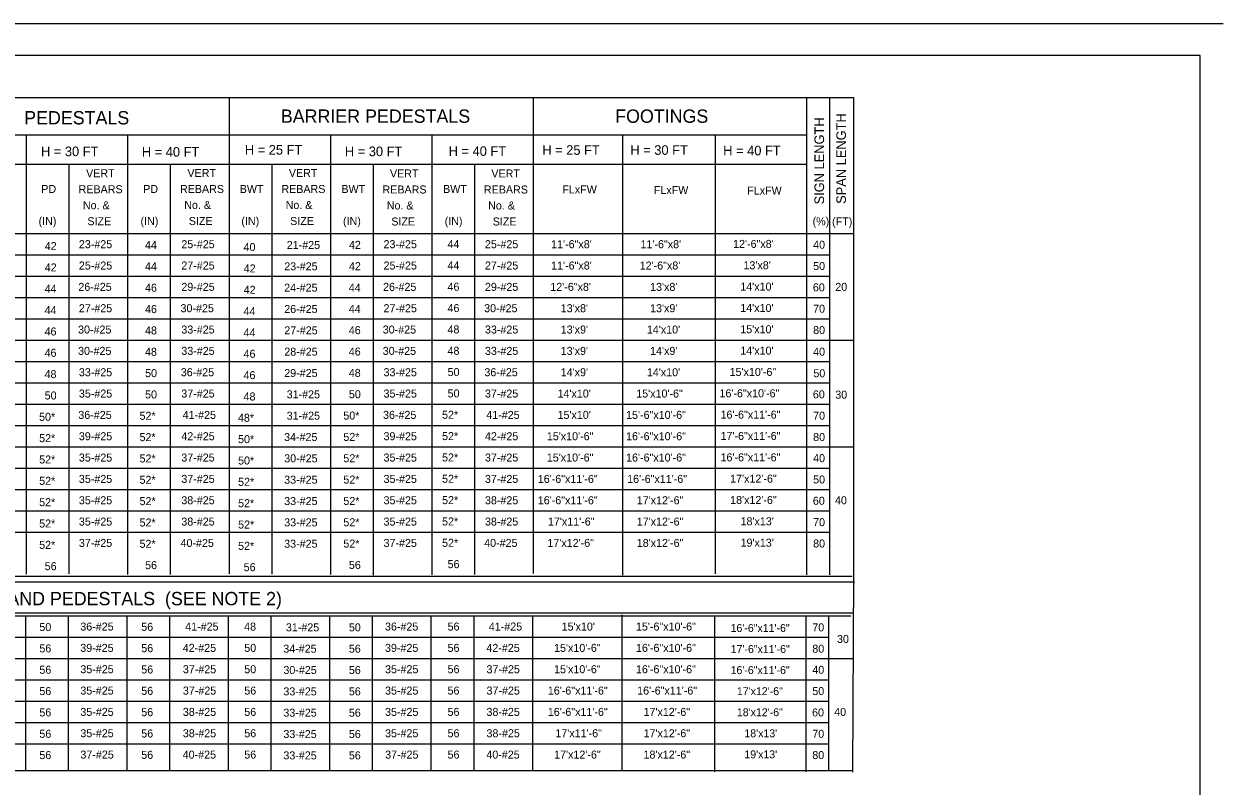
# Model space of a CAD drawing. Extents: x -17866409 to 26050223, y -3454119 to 12035012.
# Drawn here: x 31.44 to 68.89, y 19.52 to 43.33 of the extents above; entities that cross this region are included whole.
import ezdxf

# ---------------------------------------------------------------- set-up
doc = ezdxf.new("R2010")
doc.units = 0
doc.layers.add('1', color=7, linetype='Continuous')
doc.layers.add('2', color=7, linetype='Continuous')

msp = doc.modelspace()

# ---------------------------------------------------------------- linework, layer by layer
at = {"layer": '1'}
for p, q in [((68.892, 43.325), (0, 43.325)), ((68.183, 42.342), (3.6, 42.342)), ((68.183, 1.017), (68.183, 42.342))]:
    msp.add_line(p, q, dxfattribs=at)
at = {"layer": '2'}
for p, q in [((9.106, 41.029), (57.356, 41.029)), ((37.856, 26.149), (37.856, 41.029)), ((47.356, 26.154), (47.356, 41.029)), ((55.897, 26.12), (55.897, 41.029)), ((56.606, 26.117), (56.606, 41.029)), ((57.356, 26.118), (57.356, 41.029)), ((11.106, 39.862), (55.897, 39.862)), ((31.522, 26.132), (31.522, 39.862)), ((34.689, 26.13), (34.689, 39.862)), ((41.022, 26.129), (41.022, 39.862)), ((44.189, 26.117), (44.189, 39.862)), ((50.147, 26.107), (50.147, 39.862)), ((53.039, 26.145), (53.039, 39.862)), ((20.356, 38.945), (43.314, 38.945)), ((32.856, 26.149), (32.856, 38.945)), ((36.022, 26.13), (36.022, 38.945)), ((39.189, 26.139), (39.189, 38.945)), ((42.356, 26.107), (42.356, 38.945)), ((43.331, 38.945), (55.897, 38.945)), ((45.522, 26.126), (45.522, 38.945)), ((9.106, 36.779), (57.356, 36.779)), ((10.106, 36.112), (56.606, 36.112)), ((10.106, 35.445), (56.606, 35.445)), ((10.106, 34.779), (56.606, 34.779)), ((10.106, 34.112), (56.606, 34.112)), ((9.106, 33.445), (57.356, 33.445)), ((10.106, 32.779), (56.606, 32.779)), ((10.106, 32.112), (56.606, 32.112)), ((10.106, 31.445), (56.606, 31.445)), ((10.106, 30.779), (56.606, 30.779)), ((9.106, 30.112), (57.356, 30.112)), ((10.106, 29.445), (56.606, 29.445)), ((10.106, 28.779), (56.606, 28.779)), ((10.106, 28.112), (56.606, 28.112)), ((10.082, 27.445), (56.582, 27.445)), ((9.047, 26.072), (57.311, 26.072)), ((9.13, 25.892), (57.38, 25.892)), ((57.333, 19.95), (57.356, 26.118)), ((9.067, 24.83), (57.267, 24.83)), ((9.101, 24.93), (57.351, 24.93)), ((31.498, 20.005), (31.498, 24.807)), ((32.831, 19.977), (32.831, 24.807)), ((34.664, 19.977), (34.664, 24.807)), ((35.998, 19.991), (35.998, 24.846)), ((37.831, 20.005), (37.831, 24.807)), ((39.164, 19.977), (39.164, 24.846)), ((40.998, 19.977), (40.998, 24.826)), ((42.331, 20.005), (42.331, 24.826)), ((44.164, 19.991), (44.164, 24.826)), ((45.498, 19.991), (45.498, 24.846)), ((47.331, 19.977), (47.331, 24.826)), ((50.123, 19.991), (50.123, 24.861)), ((53.014, 19.964), (53.014, 24.826)), ((55.873, 19.964), (55.873, 24.826)), ((56.581, 19.991), (56.581, 24.833)), ((10.081, 24.166), (56.581, 24.166)), ((9.081, 23.499), (57.331, 23.499)), ((10.081, 22.833), (56.581, 22.833)), ((10.081, 22.166), (56.581, 22.166)), ((10.081, 21.499), (56.581, 21.499)), ((10.081, 20.833), (56.581, 20.833)), ((9.065, 19.997), (57.329, 19.997))]:
    msp.add_line(p, q, dxfattribs=at)

# ---------------------------------------------------------------- texts
for s, height, p in [('PEDESTALS', 0.4166, (31.447, 40.187)), ('BARRIER PEDESTALS', 0.41665, (39.464, 40.237)), ('FOOTINGS', 0.4166, (49.906, 40.237)), ('H = 30 FT', 0.3, (31.972, 39.195)), ('H = 40 FT', 0.3, (35.122, 39.179)), ('H = 25 FT', 0.3, (38.339, 39.245)), ('H = 30 FT', 0.3, (41.464, 39.195)), ('H = 40 FT', 0.3, (44.706, 39.204)), ('H = 25 FT', 0.3, (47.631, 39.237)), ('H = 30 FT', 0.3, (50.381, 39.237)), ('H = 40 FT', 0.3, (53.281, 39.22)), ('VERT', 0.25, (33.381, 38.537)), ('VERT', 0.25, (36.547, 38.545)), ('VERT', 0.25, (39.714, 38.545)), ('VERT', 0.25, (42.872, 38.529)), ('VERT', 0.25, (46.039, 38.529)), ('PD', 0.25, (31.981, 38.045)), ('REBARS', 0.25, (33.147, 38.037)), ('PD', 0.25, (35.164, 38.045)), ('REBARS', 0.25, (36.314, 38.045)), ('BWT', 0.25, (38.181, 38.045)), ('REBARS', 0.25, (39.481, 38.045)), ('BWT', 0.25, (41.356, 38.045)), ('REBARS', 0.25, (42.639, 38.029)), ('BWT', 0.25, (44.531, 38.045)), ('REBARS', 0.25, (45.806, 38.029)), ('FLxFW', 0.25, (48.256, 38.029)), ('FLxFW', 0.25, (51.114, 38.012)), ('FLxFW', 0.25, (54.031, 37.995)), ('No. &', 0.25, (33.281, 37.537)), ('No. &', 0.25, (36.447, 37.545)), ('No. &', 0.25, (39.614, 37.545)), ('No. &', 0.25, (42.772, 37.529)), ('No. &', 0.25, (45.939, 37.529)), ('(IN)', 0.25, (31.897, 37.045)), ('SIZE', 0.25, (33.422, 37.037)), ('(IN)', 0.25, (35.081, 37.045)), ('SIZE', 0.25, (36.589, 37.045)), ('(IN)', 0.25, (38.231, 37.045)), ('SIZE', 0.25, (39.756, 37.045)), ('(IN)', 0.25, (41.406, 37.045)), ('SIZE', 0.25, (42.914, 37.029)), ('(IN)', 0.25, (44.581, 37.045)), ('SIZE', 0.25, (46.081, 37.029)), ('(%)', 0.25, (56.072, 37.037)), ('(FT)', 0.25, (56.681, 37.029)), ('42', 0.25, (32.089, 36.26)), ('23-#25', 0.25, (33.156, 36.32)), ('44', 0.25, (35.22, 36.292)), ('25-#25', 0.25, (36.356, 36.32)), ('40', 0.25, (38.299, 36.229)), ('21-#25', 0.25, (39.649, 36.295)), ('42', 0.25, (41.591, 36.299)), ('23-#25', 0.25, (42.672, 36.32)), ('44', 0.25, (44.669, 36.324)), ('25-#25', 0.25, (45.839, 36.32)), ('11\'-6"x8\'', 0.25, (47.906, 36.32)), ('11\'-6"x8\'', 0.25, (50.697, 36.32)), ('12\'-6"x8\'', 0.25, (53.589, 36.329)), ('40', 0.25, (56.089, 36.304)), ('42', 0.25, (32.089, 35.594)), ('25-#25', 0.25, (33.156, 35.654)), ('44', 0.25, (35.22, 35.626)), ('27-#25', 0.25, (36.356, 35.654)), ('42', 0.25, (38.304, 35.562)), ('23-#25', 0.25, (39.571, 35.629)), ('42', 0.25, (41.591, 35.633)), ('25-#25', 0.25, (42.672, 35.654)), ('44', 0.25, (44.669, 35.658)), ('27-#25', 0.25, (45.839, 35.654)), ('11\'-6"x8\'', 0.25, (47.906, 35.654)), ('12\'-6"x8\'', 0.25, (50.672, 35.654)), ("13'x8'", 0.25, (53.914, 35.662)), ('50', 0.25, (56.089, 35.637)), ('26-#25', 0.25, (33.139, 34.987)), ('46', 0.25, (35.221, 34.959)), ('29-#25', 0.25, (36.356, 34.987)), ('24-#25', 0.25, (39.568, 34.962)), ('44', 0.25, (41.586, 34.966)), ('26-#25', 0.25, (42.656, 34.987)), ('46', 0.25, (44.67, 34.991)), ('29-#25', 0.25, (45.839, 34.987)), ('12\'-6"x8\'', 0.25, (47.881, 34.987)), ("13'x8'", 0.25, (50.997, 34.987)), ("14'x10'", 0.25, (53.814, 34.995)), ('60', 0.25, (56.081, 34.97)), ('20', 0.25, (56.781, 34.987)), ('44', 0.25, (32.084, 34.927)), ('42', 0.25, (38.304, 34.896)), ('44', 0.25, (32.084, 34.26)), ('27-#25', 0.25, (33.156, 34.32)), ('46', 0.25, (35.221, 34.292)), ('30-#25', 0.25, (36.331, 34.32)), ('44', 0.25, (38.299, 34.229)), ('26-#25', 0.25, (39.57, 34.295)), ('44', 0.25, (41.586, 34.299)), ('27-#25', 0.25, (42.672, 34.32)), ('46', 0.25, (44.67, 34.324)), ('30-#25', 0.25, (45.814, 34.32)), ("13'x8'", 0.25, (48.206, 34.32)), ("13'x9'", 0.25, (50.997, 34.32)), ("14'x10'", 0.25, (53.814, 34.329)), ('70', 0.25, (56.089, 34.304)), ('46', 0.25, (32.084, 33.594)), ('30-#25', 0.25, (33.131, 33.654)), ('48', 0.25, (35.221, 33.626)), ('33-#25', 0.25, (36.356, 33.654)), ('44', 0.25, (38.299, 33.562)), ('27-#25', 0.25, (39.573, 33.629)), ('46', 0.25, (41.586, 33.633)), ('30-#25', 0.25, (42.647, 33.654)), ('48', 0.25, (44.67, 33.658)), ('33-#25', 0.25, (45.839, 33.654)), ("13'x9'", 0.25, (48.206, 33.654)), ("14'x10'", 0.25, (50.897, 33.654)), ("15'x10'", 0.25, (53.814, 33.662)), ('80', 0.25, (56.089, 33.637)), ('46', 0.25, (32.084, 32.927)), ('30-#25', 0.25, (33.131, 32.987)), ('48', 0.25, (35.221, 32.959)), ('33-#25', 0.25, (36.356, 32.987)), ('46', 0.25, (38.299, 32.896)), ('28-#25', 0.25, (39.572, 32.962)), ('46', 0.25, (41.586, 32.966)), ('30-#25', 0.25, (42.647, 32.987)), ('48', 0.25, (44.67, 32.991)), ('33-#25', 0.25, (45.839, 32.987)), ("13'x9'", 0.25, (48.206, 32.987)), ("14'x9'", 0.25, (50.997, 32.987)), ("14'x10'", 0.25, (53.814, 32.995)), ('40', 0.25, (56.089, 32.962)), ('15\'x10\'-6"', 0.25, (53.481, 32.329)), ('48', 0.25, (32.084, 32.26)), ('33-#25', 0.25, (33.156, 32.32)), ('50', 0.25, (35.224, 32.292)), ('36-#25', 0.25, (36.339, 32.32)), ('46', 0.25, (38.299, 32.229)), ('29-#25', 0.25, (39.57, 32.295)), ('48', 0.25, (41.586, 32.299)), ('33-#25', 0.25, (42.672, 32.32)), ('50', 0.25, (44.673, 32.324)), ('36-#25', 0.25, (45.822, 32.32)), ("14'x9'", 0.25, (48.206, 32.32)), ("14'x10'", 0.25, (50.897, 32.32)), ('50', 0.25, (56.097, 32.287)), ('50', 0.25, (32.088, 31.594)), ('35-#25', 0.25, (33.156, 31.654)), ('50', 0.25, (35.224, 31.626)), ('37-#25', 0.25, (36.356, 31.654)), ('31-#25', 0.25, (39.646, 31.629)), ('50', 0.25, (41.59, 31.633)), ('35-#25', 0.25, (42.672, 31.654)), ('50', 0.25, (44.673, 31.658)), ('37-#25', 0.25, (45.839, 31.654)), ("14'x10'", 0.25, (48.106, 31.654)), ('15\'x10\'-6"', 0.25, (50.564, 31.654)), ('16\'-6"x10\'-6"', 0.25, (53.164, 31.662)), ('60', 0.25, (56.081, 31.629)), ('30', 0.25, (56.781, 31.62)), ('48', 0.25, (38.299, 31.562)), ('50*', 0.25, (31.913, 30.927)), ('36-#25', 0.25, (33.139, 30.987)), ('52*', 0.25, (35.051, 30.959)), ('41-#25', 0.25, (36.397, 30.987)), ('48*', 0.25, (38.125, 30.896)), ('31-#25', 0.25, (39.646, 30.962)), ('50*', 0.25, (41.415, 30.966)), ('36-#25', 0.25, (42.656, 30.987)), ('52*', 0.25, (44.5, 30.991)), ('41-#25', 0.25, (45.881, 30.987)), ("15'x10'", 0.25, (48.106, 30.987)), ('15\'-6"x10\'-6"', 0.25, (50.247, 30.987)), ('16\'-6"x11\'-6"', 0.25, (53.197, 30.995)), ('70', 0.25, (56.089, 30.962)), ('52*', 0.25, (31.915, 30.26)), ('39-#25', 0.25, (33.156, 30.32)), ('52*', 0.25, (35.051, 30.292)), ('42-#25', 0.25, (36.356, 30.32)), ('50*', 0.25, (38.128, 30.229)), ('34-#25', 0.25, (39.565, 30.295)), ('52*', 0.25, (41.416, 30.299)), ('39-#25', 0.25, (42.672, 30.32)), ('52*', 0.25, (44.5, 30.324)), ('42-#25', 0.25, (45.839, 30.32)), ('15\'x10\'-6"', 0.25, (47.772, 30.32)), ('16\'-6"x10\'-6"', 0.25, (50.247, 30.32)), ('17\'-6"x11\'-6"', 0.25, (53.197, 30.329)), ('80', 0.25, (56.089, 30.295)), ('52*', 0.25, (31.915, 29.594)), ('35-#25', 0.25, (33.156, 29.654)), ('52*', 0.25, (35.051, 29.626)), ('37-#25', 0.25, (36.356, 29.654)), ('50*', 0.25, (38.128, 29.562)), ('30-#25', 0.25, (39.569, 29.629)), ('52*', 0.25, (41.416, 29.633)), ('35-#25', 0.25, (42.672, 29.654)), ('52*', 0.25, (44.5, 29.658)), ('37-#25', 0.25, (45.839, 29.654)), ('15\'x10\'-6"', 0.25, (47.772, 29.654)), ('16\'-6"x10\'-6"', 0.25, (50.247, 29.654)), ('16\'-6"x11\'-6"', 0.25, (53.197, 29.662)), ('40', 0.25, (56.089, 29.637)), ('35-#25', 0.25, (33.156, 28.987)), ('52*', 0.25, (35.051, 28.959)), ('37-#25', 0.25, (36.356, 28.987)), ('33-#25', 0.25, (39.568, 28.962)), ('52*', 0.25, (41.416, 28.966)), ('35-#25', 0.25, (42.672, 28.987)), ('52*', 0.25, (44.5, 28.991)), ('37-#25', 0.25, (45.839, 28.987)), ('16\'-6"x11\'-6"', 0.25, (47.489, 28.987)), ('16\'-6"x11\'-6"', 0.25, (50.281, 28.987)), ('17\'x12\'-6"', 0.25, (53.497, 28.995)), ('50', 0.25, (56.089, 28.97)), ('52*', 0.25, (31.915, 28.927)), ('52*', 0.25, (38.129, 28.896)), ('52*', 0.25, (31.915, 28.26)), ('35-#25', 0.25, (33.156, 28.32)), ('52*', 0.25, (35.051, 28.292)), ('38-#25', 0.25, (36.356, 28.32)), ('52*', 0.25, (38.129, 28.229)), ('33-#25', 0.25, (39.568, 28.295)), ('52*', 0.25, (41.416, 28.299)), ('35-#25', 0.25, (42.672, 28.32)), ('52*', 0.25, (44.5, 28.324)), ('38-#25', 0.25, (45.839, 28.32)), ('16\'-6"x11\'-6"', 0.25, (47.489, 28.32)), ('17\'x12\'-6"', 0.25, (50.581, 28.32)), ('18\'x12\'-6"', 0.25, (53.497, 28.329)), ('60', 0.25, (56.081, 28.304)), ('40', 0.25, (56.772, 28.32)), ('52*', 0.25, (31.915, 27.594)), ('35-#25', 0.25, (33.156, 27.654)), ('52*', 0.25, (35.051, 27.626)), ('38-#25', 0.25, (36.356, 27.654)), ('52*', 0.25, (38.129, 27.562)), ('33-#25', 0.25, (39.568, 27.629)), ('52*', 0.25, (41.416, 27.633)), ('35-#25', 0.25, (42.672, 27.654)), ('52*', 0.25, (44.5, 27.658)), ('38-#25', 0.25, (45.839, 27.654)), ('17\'x11\'-6"', 0.25, (47.806, 27.654)), ('17\'x12\'-6"', 0.25, (50.581, 27.654)), ("18'x13'", 0.25, (53.822, 27.662)), ('70', 0.25, (56.089, 27.637)), ('52*', 0.25, (31.915, 26.927)), ('37-#25', 0.25, (33.156, 26.987)), ('52*', 0.25, (35.051, 26.959)), ('40-#25', 0.25, (36.331, 26.987)), ('52*', 0.25, (38.129, 26.896)), ('33-#25', 0.25, (39.568, 26.962)), ('52*', 0.25, (41.416, 26.966)), ('37-#25', 0.25, (42.672, 26.987)), ('52*', 0.25, (44.5, 26.991)), ('40-#25', 0.25, (45.814, 26.987)), ('17\'x12\'-6"', 0.25, (47.789, 26.987)), ('18\'x12\'-6"', 0.25, (50.581, 26.987)), ("19'x13'", 0.25, (53.822, 26.995)), ('80', 0.25, (56.089, 26.97)), ('56', 0.25, (32.088, 26.26)), ('56', 0.25, (35.224, 26.292)), ('56', 0.25, (38.303, 26.229)), ('56', 0.25, (41.59, 26.299)), ('56', 0.25, (44.673, 26.324)), ('* ALTERNATIVE POSTS AND PEDESTALS  (SEE NOTE 2)', 0.41665, (24.544, 25.164)), ('50', 0.25, (31.922, 24.358)), ('36-#25', 0.25, (33.2, 24.374)), ('56', 0.25, (35.105, 24.366)), ('41-#25', 0.25, (36.477, 24.374)), ('48', 0.25, (38.318, 24.374)), ('31-#25', 0.25, (39.622, 24.349)), ('50', 0.25, (41.588, 24.349)), ('36-#25', 0.25, (42.717, 24.374)), ('56', 0.25, (44.672, 24.374)), ('41-#25', 0.25, (45.96, 24.374)), ("15'x10'", 0.25, (48.234, 24.374)), ('15\'-6"x10\'-6"', 0.25, (50.556, 24.374)), ('16\'-6"x11\'-6"', 0.24674, (53.511, 24.33)), ('70', 0.25, (56.064, 24.349)), ('30', 0.25, (56.835, 23.987)), ('56', 0.25, (31.922, 23.691)), ('39-#25', 0.25, (33.2, 23.708)), ('56', 0.25, (35.105, 23.699)), ('42-#25', 0.25, (36.401, 23.708)), ('50', 0.25, (38.322, 23.708)), ('34-#25', 0.25, (39.54, 23.683)), ('56', 0.25, (41.588, 23.683)), ('39-#25', 0.25, (42.717, 23.708)), ('56', 0.25, (44.672, 23.708)), ('42-#25', 0.25, (45.884, 23.708)), ('15\'x10\'-6"', 0.25, (47.998, 23.708)), ('16\'-6"x10\'-6"', 0.25, (50.556, 23.708)), ('17\'-6"x11\'-6"', 0.24674, (53.513, 23.672)), ('80', 0.25, (56.064, 23.683)), ('56', 0.25, (31.922, 23.024)), ('35-#25', 0.25, (33.202, 23.041)), ('56', 0.25, (35.105, 23.033)), ('37-#25', 0.25, (36.404, 23.041)), ('50', 0.25, (38.322, 23.041)), ('30-#25', 0.25, (39.544, 23.016)), ('56', 0.25, (41.588, 23.016)), ('35-#25', 0.25, (42.719, 23.041)), ('56', 0.25, (44.672, 23.041)), ('37-#25', 0.25, (45.888, 23.041)), ('15\'x10\'-6"', 0.25, (47.998, 23.041)), ('16\'-6"x10\'-6"', 0.25, (50.556, 23.041)), ('16\'-6"x11\'-6"', 0.24674, (53.511, 23.015)), ('40', 0.25, (56.064, 23.024)), ('56', 0.25, (31.922, 22.358)), ('35-#25', 0.25, (33.202, 22.374)), ('56', 0.25, (35.105, 22.366)), ('37-#25', 0.25, (36.404, 22.374)), ('56', 0.25, (38.322, 22.374)), ('33-#25', 0.25, (39.543, 22.349)), ('56', 0.25, (41.588, 22.349)), ('35-#25', 0.25, (42.719, 22.374)), ('56', 0.25, (44.672, 22.374)), ('37-#25', 0.25, (45.888, 22.374)), ('16\'-6"x11\'-6"', 0.25, (47.803, 22.374)), ('16\'-6"x11\'-6"', 0.25, (50.594, 22.374)), ('17\'x12\'-6"', 0.2467, (53.708, 22.357)), ('50', 0.25, (56.064, 22.358)), ('56', 0.25, (31.922, 21.691)), ('35-#25', 0.25, (33.202, 21.708)), ('56', 0.25, (35.105, 21.699)), ('38-#25', 0.25, (36.403, 21.708)), ('56', 0.25, (38.322, 21.708)), ('33-#25', 0.25, (39.543, 21.683)), ('56', 0.25, (41.588, 21.683)), ('35-#25', 0.25, (42.719, 21.708)), ('56', 0.25, (44.672, 21.708)), ('38-#25', 0.25, (45.887, 21.708)), ('16\'-6"x11\'-6"', 0.25, (47.803, 21.708)), ('17\'x12\'-6"', 0.25, (50.792, 21.708)), ('18\'x12\'-6"', 0.2467, (53.708, 21.699)), ('60', 0.25, (56.056, 21.691)), ('40', 0.25, (56.748, 21.708)), ('56', 0.25, (31.922, 21.024)), ('35-#25', 0.25, (33.202, 21.041)), ('56', 0.25, (35.105, 21.033)), ('38-#25', 0.25, (36.403, 21.041)), ('56', 0.25, (38.322, 21.041)), ('33-#25', 0.25, (39.543, 21.016)), ('56', 0.25, (41.588, 21.016)), ('35-#25', 0.25, (42.719, 21.041)), ('56', 0.25, (44.672, 21.041)), ('38-#25', 0.25, (45.887, 21.041)), ('17\'x11\'-6"', 0.25, (48.038, 21.041)), ('17\'x12\'-6"', 0.25, (50.792, 21.041)), ("18'x13'", 0.2467, (53.942, 21.041)), ('70', 0.25, (56.064, 21.024)), ('56', 0.25, (31.922, 20.358)), ('37-#25', 0.25, (33.204, 20.374)), ('56', 0.25, (35.105, 20.366)), ('40-#25', 0.25, (36.399, 20.374)), ('56', 0.25, (38.322, 20.374)), ('33-#25', 0.25, (39.543, 20.349)), ('56', 0.25, (41.588, 20.349)), ('37-#25', 0.25, (42.721, 20.374)), ('56', 0.25, (44.672, 20.374)), ('40-#25', 0.25, (45.883, 20.374)), ('17\'x12\'-6"', 0.25, (48, 20.374)), ('18\'x12\'-6"', 0.25, (50.791, 20.374)), ("19'x13'", 0.2467, (53.941, 20.383)), ('80', 0.25, (56.064, 20.358))]:
    msp.add_text(s, height=height, dxfattribs=at).set_placement(p)
for s, p in [('SPAN LENGTH', (57.114, 37.704)), ('SIGN LENGTH', (56.431, 37.687))]:
    msp.add_text(s, height=0.3, rotation=90, dxfattribs=at).set_placement(p)

doc.saveas('drawing.dxf')
